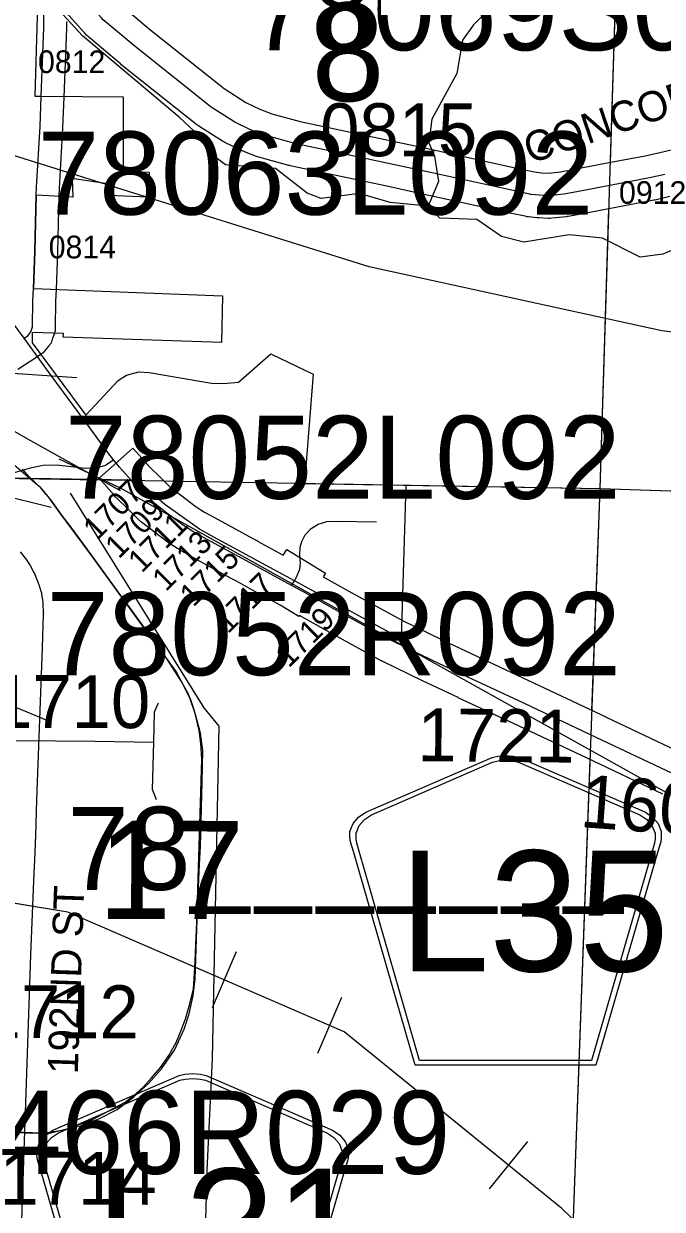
# Model space of a CAD drawing. Extents: x -132.8 to -73.3, y -60 to -26.
# Drawn here: x -120.744 to -119.898, y -53.272 to -51.702 of the extents above; entities that cross this region are included whole.
import ezdxf

# ---------------------------------------------------------------- set-up
doc = ezdxf.new("R2010")
doc.units = 0
for name, color, linetype in [('tdCoCityStreetMajor', 7, 'Continuous'), ('tdCoCityStreetMinor', 7, 'Continuous'), ('tdCoCorpBndry', 7, 'Continuous'), ('tdCoHydroRiver', 7, 'Continuous'), ('tdCoInstTxt', 7, 'Continuous'), ('tdCoPipe', 7, 'Continuous'), ('tdCoRRCL', 7, 'Continuous'), ('tdCoSecRdNmbr', 7, 'Continuous'), ('tdCoSecRdTxt', 7, 'Continuous'), ('tdCoSecRteBand', 7, 'Continuous'), ('tdCoSecRteCL', 7, 'Continuous'), ('tdCoSectLine', 7, 'Continuous'), ('tdCoSectLinePart', 7, 'Continuous'), ('tdCoSectNmbr', 7, 'Continuous'), ('tdCoShieldCoRte', 7, 'Continuous'), ('tdCoShieldCoRteHrd', 7, 'Continuous'), ('tdCoStrucPriMaintName', 7, 'Continuous'), ('tdCoSurfAsphalt', 7, 'Continuous'), ('tdCoSurfBitum', 7, 'Continuous'), ('tdCoSurfConc', 7, 'Continuous'), ('tdCoSurfConcUnbanded', 7, 'Continuous'), ('tdCoSurfGravel', 7, 'Continuous')]:
    doc.layers.add(name, color=color, linetype=linetype)

msp = doc.modelspace()

# ---------------------------------------------------------------- linework, layer by layer
at = {"layer": 'tdCoCityStreetMajor'}
msp.add_lwpolyline([(-120.6017, -52.3067), (-120.617, -52.2894), (-120.6248, -52.2797), (-120.6325, -52.2701), (-120.6564, -52.2371), (-120.6786, -52.2067), (-120.7077, -52.1678), (-120.7433, -52.1186), (-120.7581, -52.0982), (-120.8243, -52.009), (-120.927, -51.8699), (-120.9535, -51.834), (-120.9769, -51.8032)], dxfattribs=at)
at = {"layer": 'tdCoCityStreetMinor'}
for points in [[(-120.7873, -52.3034), (-120.7673, -52.2994), (-120.7333, -52.2898), (-120.718, -52.2866), (-120.7, -52.2863), (-120.6812, -52.2883), (-120.6623, -52.2905), (-120.648, -52.2903), (-120.6364, -52.2871), (-120.6248, -52.2797)], [(-120.3853, -52.4396), (-120.3829, -52.4356), (-120.3782, -52.4245), (-120.377, -52.4161), (-120.3779, -52.4058), (-120.3775, -52.3954), (-120.3755, -52.3878), (-120.3708, -52.3789), (-120.3631, -52.3703), (-120.3538, -52.3646), (-120.3422, -52.3611), (-120.3289, -52.3606), (-120.2766, -52.3616)]]:
    msp.add_lwpolyline(points, dxfattribs=at)
at = {"layer": 'tdCoCorpBndry'}
msp.add_lwpolyline([(-120.7232, -51.5858), (-120.7293, -51.7981), (-120.7208, -51.7982), (-120.6119, -51.7988), (-120.6119, -51.8983), (-120.5776, -51.8989), (-120.5788, -51.932), (-120.6317, -51.9297), (-120.6327, -51.9142), (-120.6795, -51.9071), (-120.6789, -51.9317), (-120.7273, -51.9293), (-120.7292, -52.0033), (-120.7311, -52.0527), (-120.4803, -52.0623), (-120.4818, -52.1241), (-120.6914, -52.1171), (-120.6913, -52.1124), (-120.7326, -52.111), (-120.7329, -52.1245), (-120.6618, -52.2205), (-120.6188, -52.1747), (-120.6077, -52.1673), (-120.5913, -52.1632), (-120.5777, -52.1641), (-120.4949, -52.1781), (-120.4791, -52.1787), (-120.4595, -52.1768), (-120.4164, -52.1394), (-120.3605, -52.1662), (-120.3717, -52.3108), (-120.2377, -52.3132), (-120.2436, -52.5164), (-120.3853, -52.4396), (-120.4921, -52.3818), (-120.511, -52.3713), (-120.5569, -52.3389), (-120.5929, -52.3068), (-120.6017, -52.3067), (-120.7874, -52.3034)], dxfattribs=at)
at = {"layer": 'tdCoHydroRiver'}
for points in [[(-119.8566, -51.3835), (-119.9158, -51.4151), (-119.9272, -51.4274), (-119.9372, -51.4461), (-119.9593, -51.5038), (-119.9777, -51.5444), (-120.0187, -51.6032), (-120.0457, -51.6072), (-120.0581, -51.599), (-120.0835, -51.6031), (-120.0964, -51.6153), (-120.1081, -51.6387), (-120.112, -51.667), (-120.1477, -51.7039), (-120.1625, -51.724), (-120.17, -51.768), (-120.2031, -51.8286), (-120.2071, -51.8601), (-120.1997, -51.8776), (-120.1943, -51.9109), (-120.2078, -51.9437)], [(-120.2078, -51.9437), (-120.2582, -51.9391), (-120.2989, -51.927), (-120.3496, -51.9335), (-120.3684, -51.9267), (-120.4101, -51.894), (-120.4763, -51.8891), (-120.4871, -51.8809), (-120.4977, -51.8633), (-120.5377, -51.8259), (-120.6658, -51.7183), (-120.7578, -51.618), (-120.7684, -51.6004), (-120.7694, -51.5798), (-120.7846, -51.5557), (-120.8, -51.5411), (-121.0683, -51.5418), (-121.1168, -51.5263), (-121.1402, -51.5146)], [(-119.7523, -51.9086), (-119.77, -51.9223), (-119.8164, -51.9447), (-119.8358, -51.9632), (-119.8507, -51.988), (-119.897, -52.0073), (-119.9271, -52.0112), (-119.9769, -51.9862), (-120.021, -51.9818), (-120.0812, -51.9912), (-120.111, -51.9841), (-120.1436, -51.9612), (-120.1925, -51.9598), (-120.2078, -51.9437)], [(-120.5124, -53.6489), (-120.5009, -53.2201), (-120.4938, -53.072), (-120.4851, -52.632), (-120.505, -52.6078), (-120.6821, -52.3237)]]:
    msp.add_lwpolyline(points, dxfattribs=at)
at = {"layer": 'tdCoInstTxt'}
msp.add_lwpolyline([(-119.6004, -52.1468), (-119.8985, -52.1087), (-120.2863, -52.0241), (-120.7731, -51.872), (-120.8087, -51.8239)], dxfattribs=at)
msp.add_lwpolyline([(-119.6004, -52.1468), (-119.8985, -52.1087), (-120.2863, -52.0241), (-120.7731, -51.872), (-120.8087, -51.8239)], dxfattribs=at)
at = {"layer": 'tdCoPipe'}
for p, q in [((-120.4624, -52.9309), (-120.4943, -53.0049)), ((-120.3227, -52.9913), (-120.3547, -53.0654)), ((-120.0763, -53.1821), (-120.1271, -53.2446))]:
    msp.add_line(p, q, dxfattribs=at)
for points in [[(-119.7966, -53.496), (-120.031, -53.2709), (-120.3193, -53.0367), (-120.6853, -52.8785), (-121.0012, -52.8266), (-121.4905, -52.4057), (-121.3998, -51.5572), (-121.2369, -50.9128), (-120.9144, -50.4185), (-120.4009, -49.5883), (-120.2556, -49.2317), (-120.1948, -48.5733), (-120.2234, -47.9788), (-119.9584, -47.7616), (-119.9471, -47.3844)], [(-120.4784, -52.968), (-120.6853, -52.8785), (-120.7602, -52.8662)], [(-120.1017, -53.2134), (-120.3193, -53.0367), (-120.3387, -53.0283)]]:
    msp.add_lwpolyline(points, dxfattribs=at)
at = {"layer": 'tdCoRRCL'}
msp.add_line((-120.7391, -52.2518), (-120.616, -52.32), dxfattribs=at)
for points in [[(-121.1776, -51.8759), (-120.848, -52.189), (-120.7391, -52.2518)], [(-120.6972, -52.2782), (-120.6161, -52.3166), (-119.5675, -52.901), (-119.4875, -52.922), (-119.4101, -52.9193), (-119.3464, -52.8957), (-119.2742, -52.8534), (-118.8703, -52.5563), (-118.7896, -52.5458), (-118.7219, -52.5523), (-118.6702, -52.5695), (-118.4084, -52.6978), (-118.1016, -52.8573), (-117.8806, -52.9782), (-117.8049, -53.0417), (-117.7743, -53.0804), (-117.6699, -53.3151)], [(-120.8232, -53.1664), (-120.7098, -53.1712), (-120.6833, -53.1642), (-120.6526, -53.1529), (-120.6094, -53.1299), (-120.5951, -53.1183), (-120.5848, -53.1091), (-120.5744, -53.0976), (-120.5628, -53.0842), (-120.5516, -53.0684), (-120.5417, -53.0511), (-120.5356, -53.036), (-120.5296, -53.0198), (-120.5236, -52.9996), (-120.5189, -52.98), (-120.5172, -52.9521), (-120.5147, -52.8917), (-120.5079, -52.6759), (-120.5092, -52.6552), (-120.5115, -52.6381), (-120.5168, -52.6155), (-120.5187, -52.6081), (-120.522, -52.5985), (-120.526, -52.5889), (-120.5338, -52.575), (-120.542, -52.5597), (-120.6036, -52.4748), (-120.6201, -52.4526), (-120.6545, -52.4049), (-120.6803, -52.3702), (-120.6934, -52.3528), (-120.7075, -52.333), (-120.714, -52.3253), (-120.7214, -52.3166), (-120.7287, -52.3103), (-120.7566, -52.2868)], [(-120.7727, -53.169), (-120.7334, -53.171), (-120.7124, -53.17), (-120.6909, -53.1666), (-120.6687, -53.1613), (-120.6445, -53.1519), (-120.6202, -53.1396), (-120.5979, -53.1228), (-120.5787, -53.1052), (-120.5612, -53.0858), (-120.5441, -53.0612), (-120.5313, -53.0334), (-120.5245, -53.013), (-120.5192, -52.9889), (-120.5169, -52.9666), (-120.5135, -52.8751), (-120.5108, -52.8155), (-120.5098, -52.7917), (-120.5074, -52.7063), (-120.5067, -52.6643), (-120.5098, -52.6413), (-120.5161, -52.6169), (-120.5237, -52.5946), (-120.535, -52.5731), (-120.5588, -52.5361), (-120.5782, -52.5107), (-120.655, -52.4048), (-120.6967, -52.3484), (-120.7114, -52.328), (-120.7198, -52.3178), (-120.7362, -52.3027), (-120.7455, -52.292)]]:
    msp.add_lwpolyline(points, dxfattribs=at)
at = {"layer": 'tdCoSecRteBand'}
for points in [[(-120.6179, -51.6751), (-120.5774, -51.7093), (-120.4783, -51.7881), (-120.4496, -51.8063), (-120.4312, -51.8152), (-120.4252, -51.8175), (-120.4153, -51.8214), (-120.3775, -51.8316), (-120.2504, -51.8587), (-120.2148, -51.8663), (-120.2147, -51.8663), (-120.2146, -51.8663), (-120.0849, -51.8946), (-120.0671, -51.8984), (-120.0579, -51.8995), (-120.0483, -51.8999), (-120.0324, -51.8982), (-120.0166, -51.8952), (-119.9707, -51.8865), (-119.9206, -51.877), (-119.901, -51.8725), (-119.8628, -51.8638)], [(-120.6872, -51.6994), (-120.6874, -51.7083), (-120.6874, -51.7085), (-120.6874, -51.7087), (-120.6908, -51.7993), (-120.6924, -51.8397), (-120.6924, -51.84), (-120.6924, -51.8403), (-120.697, -51.92), (-120.6973, -51.9301), (-120.6992, -52.0041), (-120.6992, -52.0042), (-120.6993, -52.0044), (-120.7011, -52.0539), (-120.7017, -52.0697), (-120.7022, -52.1041), (-120.7023, -52.1087), (-120.7037, -52.1131), (-120.706, -52.1198), (-120.7077, -52.125), (-120.7111, -52.1292), (-120.7153, -52.1344), (-120.7182, -52.1379), (-120.722, -52.1404), (-120.7267, -52.1436), (-120.7517, -52.1602)], [(-119.8876, -51.931), (-119.9078, -51.9356), (-119.9084, -51.9357), (-119.9089, -51.9358), (-119.9595, -51.9455), (-120.0054, -51.9542), (-120.0224, -51.9574), (-120.0236, -51.9576), (-120.0248, -51.9578), (-120.0443, -51.9598), (-120.0466, -51.9601), (-120.049, -51.96), (-120.0617, -51.9593), (-120.0626, -51.9593), (-120.0635, -51.9592), (-120.0752, -51.9579), (-120.0767, -51.9578), (-120.0782, -51.9574), (-120.0796, -51.9571), (-120.0976, -51.9533), (-120.0976, -51.9533), (-120.0976, -51.9533), (-120.2273, -51.925), (-120.2629, -51.9174), (-120.3908, -51.8902), (-120.3916, -51.89), (-120.3924, -51.8898), (-120.4325, -51.8789), (-120.434, -51.8785), (-120.4355, -51.8779), (-120.4469, -51.8735), (-120.454, -51.8707), (-120.4552, -51.8703), (-120.4563, -51.8698), (-120.4774, -51.8595), (-120.4789, -51.8588), (-120.4803, -51.8579), (-120.5118, -51.8379), (-120.5132, -51.837), (-120.5144, -51.836), (-120.6151, -51.756), (-120.6154, -51.7557), (-120.6158, -51.7554), (-120.6578, -51.7199), (-120.6591, -51.7189), (-120.6602, -51.7177), (-120.6631, -51.7147), (-120.6634, -51.7143), (-120.6638, -51.7139), (-120.687, -51.6877)], [(-119.8969, -52.7221), (-119.998, -52.6743), (-120.1015, -52.6255), (-120.1682, -52.5945), (-120.1683, -52.5944), (-120.1684, -52.5944), (-120.2153, -52.5722), (-120.2154, -52.5721), (-120.2156, -52.5721), (-120.2688, -52.5462), (-120.2695, -52.5459), (-120.2701, -52.5455), (-120.3382, -52.5083), (-120.3383, -52.5082), (-120.3384, -52.5081), (-120.3785, -52.4857), (-120.3794, -52.4872), (-120.4041, -52.472), (-120.412, -52.4678), (-120.4122, -52.4677), (-120.4297, -52.4585), (-120.4295, -52.4581), (-120.4629, -52.4397), (-120.469, -52.4365), (-120.5151, -52.4114), (-120.5154, -52.4113), (-120.5156, -52.4112), (-120.5343, -52.4005), (-120.5349, -52.4002), (-120.5355, -52.3998), (-120.5481, -52.392), (-120.5491, -52.3913), (-120.5501, -52.3906), (-120.5723, -52.3741), (-120.5725, -52.3739), (-120.5727, -52.3738), (-120.5877, -52.3622), (-120.5891, -52.3611), (-120.5904, -52.3598), (-120.6037, -52.3468), (-120.6214, -52.3296), (-120.6222, -52.3288), (-120.623, -52.3279), (-120.6242, -52.3265), (-120.6242, -52.3265), (-120.6441, -52.304), (-120.5991, -52.2643), (-120.5792, -52.2868), (-120.5792, -52.2868), (-120.5792, -52.2868), (-120.5792, -52.2869), (-120.5787, -52.2874), (-120.5618, -52.3039), (-120.5617, -52.3039), (-120.5617, -52.304), (-120.5497, -52.3158), (-120.5362, -52.3261), (-120.5152, -52.3418), (-120.5042, -52.3487), (-120.4863, -52.3588), (-120.4403, -52.3837), (-120.4342, -52.387), (-120.4342, -52.3871), (-120.4341, -52.3871), (-120.3999, -52.406), (-120.3952, -52.3983), (-120.3441, -52.4298), (-120.347, -52.4346), (-120.3093, -52.4557), (-120.2419, -52.4925), (-120.1895, -52.518), (-120.1428, -52.5401), (-120.0761, -52.5712), (-120.076, -52.5712), (-120.076, -52.5712), (-119.9724, -52.62), (-119.9724, -52.6201), (-119.9723, -52.6201), (-119.8713, -52.6679)], [(-120.7484, -52.4012), (-120.742, -52.4098), (-120.7417, -52.4103), (-120.7413, -52.4108), (-120.7371, -52.417), (-120.7363, -52.4182), (-120.7355, -52.4196), (-120.7306, -52.4287), (-120.7298, -52.4301), (-120.7292, -52.4316), (-120.7248, -52.4425), (-120.7243, -52.4436), (-120.7239, -52.4448), (-120.7212, -52.4535), (-120.7205, -52.4556), (-120.7202, -52.4579), (-120.7187, -52.4675), (-120.7185, -52.4691), (-120.7184, -52.4707), (-120.7179, -52.4813), (-120.7178, -52.4825), (-120.7179, -52.4838), (-120.7196, -52.5287), (-120.727, -52.7298), (-120.7285, -52.7763), (-120.7285, -52.7765), (-120.7285, -52.7766), (-120.7298, -52.8094), (-120.7305, -52.8263), (-120.7349, -52.9348), (-120.7418, -53.1436), (-120.7418, -53.1436), (-120.7418, -53.1436), (-120.7431, -53.1809), (-120.7431, -53.181), (-120.7431, -53.181), (-120.7431, -53.181), (-120.748, -53.3258)]]:
    msp.add_lwpolyline(points, dxfattribs=at)
at = {"layer": 'tdCoSecRteCL'}
msp.add_line((-120.3892, -52.4459), (-120.3853, -52.4396), dxfattribs=at)
for points in [[(-119.8943, -51.9017), (-119.9145, -51.9064), (-119.9651, -51.916), (-120.011, -51.9247), (-120.028, -51.9279), (-120.0475, -51.93), (-120.0603, -51.9294), (-120.0719, -51.9281), (-120.0733, -51.9278), (-120.0913, -51.9239), (-120.221, -51.8957), (-120.2567, -51.8881), (-120.3845, -51.8608), (-120.4246, -51.8499), (-120.4361, -51.8455), (-120.4432, -51.8428), (-120.4643, -51.8325), (-120.4957, -51.8126), (-120.5964, -51.7325), (-120.6385, -51.697), (-120.6413, -51.694), (-120.7123, -51.6137), (-120.716, -51.5974), (-120.7161, -51.5863)], [(-120.7433, -52.1186), (-120.7386, -52.1155), (-120.7344, -52.1103), (-120.7322, -52.1036), (-120.7317, -52.0689), (-120.7311, -52.0527), (-120.7292, -52.0033), (-120.7273, -51.9293), (-120.727, -51.9187), (-120.7223, -51.8385), (-120.7208, -51.7982), (-120.7174, -51.7076), (-120.7172, -51.6987), (-120.7168, -51.6778)], [(-120.3892, -52.4459), (-120.398, -52.4413), (-120.4486, -52.4134), (-120.4546, -52.4101), (-120.5008, -52.385), (-120.5196, -52.3744), (-120.5322, -52.3665), (-120.5543, -52.35), (-120.5694, -52.3384), (-120.5827, -52.3254), (-120.6005, -52.3081), (-120.6017, -52.3067), (-120.6017, -52.3067)], [(-119.7505, -52.7553), (-119.764, -52.75), (-119.7788, -52.7434), (-119.8212, -52.7244), (-119.8841, -52.695), (-119.9852, -52.6472), (-120.0888, -52.5984), (-120.1556, -52.5673), (-120.2024, -52.5451), (-120.2557, -52.5192), (-120.3238, -52.482), (-120.3741, -52.4538), (-120.3892, -52.4459)], [(-120.5715, -52.6535), (-120.5704, -52.6132), (-120.5655, -52.6013)], [(-120.7541, -52.6512), (-120.6495, -52.652), (-120.5715, -52.6535)], [(-120.5678, -52.7299), (-120.5733, -52.7159), (-120.5715, -52.6535)]]:
    msp.add_lwpolyline(points, dxfattribs=at)
at = {"layer": 'tdCoSectLine'}
for points in [[(-119.9802, -52.3177), (-119.9485, -51.3215)], [(-120.9864, -52.2999), (-119.9802, -52.3177)], [(-120.0166, -53.3198), (-119.9802, -52.3177)], [(-119.9802, -52.3177), (-118.9893, -52.35)]]:
    msp.add_lwpolyline(points, dxfattribs=at)
at = {"layer": 'tdCoSectLinePart'}
for points in [[(-119.9665, -51.8857), (-119.9499, -51.3639)], [(-119.9802, -52.3177), (-119.9684, -51.9471)], [(-120.75, -52.3041), (-120.6427, -52.306)], [(-120.372, -52.3108), (-119.9802, -52.3177)], [(-119.9909, -52.6114), (-119.9802, -52.3177)], [(-119.9802, -52.3177), (-119.7684, -52.3246)], [(-120.0166, -53.3198), (-119.9933, -52.6769)]]:
    msp.add_lwpolyline(points, dxfattribs=at)
at = {"layer": 'tdCoShieldCoRte'}
for points in [[(-120.6398, -53.5022), (-120.7217, -53.2193), (-120.7256, -53.2062), (-120.7263, -53.2003), (-120.7263, -53.1925), (-120.7221, -53.1822), (-120.7148, -53.1737), (-120.7052, -53.167), (-120.538, -53.0946), (-120.5304, -53.093), (-120.52, -53.0921), (-120.5096, -53.093), (-120.5021, -53.0946), (-120.3348, -53.167), (-120.3252, -53.1737), (-120.318, -53.1822), (-120.3137, -53.1925), (-120.3137, -53.2003), (-120.3144, -53.2062), (-120.3183, -53.2193), (-120.4003, -53.5022)], [(-120.6339, -53.4959), (-120.7137, -53.2206), (-120.7174, -53.208), (-120.7181, -53.2023), (-120.7181, -53.1948), (-120.714, -53.1849), (-120.707, -53.1768), (-120.6978, -53.1704), (-120.5372, -53.1009), (-120.53, -53.0994), (-120.52, -53.0985), (-120.51, -53.0994), (-120.5028, -53.1009), (-120.3422, -53.1704), (-120.333, -53.1768), (-120.326, -53.1849), (-120.322, -53.1948), (-120.322, -53.2023), (-120.3227, -53.208), (-120.3264, -53.2206), (-120.4061, -53.4959)]]:
    msp.add_lwpolyline(points, close=True, dxfattribs=at)
at = {"layer": 'tdCoShieldCoRteHrd'}
for points in [[(-120.2251, -53.0812), (-120.3071, -52.7983), (-120.3109, -52.7852), (-120.3117, -52.7793), (-120.3117, -52.7715), (-120.3074, -52.7611), (-120.3001, -52.7527), (-120.2906, -52.746), (-120.1233, -52.6736), (-120.1158, -52.672), (-120.1054, -52.6711), (-120.0949, -52.672), (-120.0874, -52.6736), (-119.9201, -52.746), (-119.9106, -52.7527), (-119.9033, -52.7611), (-119.899, -52.7715), (-119.899, -52.7793), (-119.8998, -52.7852), (-119.9037, -52.7983), (-119.9856, -53.0812)], [(-120.2193, -53.0749), (-120.299, -52.7996), (-120.3027, -52.787), (-120.3034, -52.7813), (-120.3034, -52.7738), (-120.2993, -52.7639), (-120.2924, -52.7558), (-120.2832, -52.7494), (-120.1226, -52.6799), (-120.1154, -52.6783), (-120.1054, -52.6775), (-120.0953, -52.6783), (-120.0881, -52.6799), (-119.9275, -52.7494), (-119.9184, -52.7558), (-119.9114, -52.7639), (-119.9073, -52.7738), (-119.9073, -52.7813), (-119.908, -52.787), (-119.9117, -52.7996), (-119.9915, -53.0749)]]:
    msp.add_lwpolyline(points, close=True, dxfattribs=at)
at = {"layer": 'tdCoStrucPriMaintName'}
for p, q in [((-120.6737, -52.1711), (-121.5022, -52.1143)), ((-120.6737, -52.1711), (-121.5022, -52.1143)), ((-120.6737, -52.1711), (-121.5022, -52.1143)), ((-120.7077, -52.3428), (-121.4594, -52.1563)), ((-120.7077, -52.3428), (-121.4594, -52.1563)), ((-120.7077, -52.3428), (-121.4594, -52.1563)), ((-120.7077, -52.627), (-121.4353, -52.3257)), ((-120.7077, -52.627), (-121.4353, -52.3257)), ((-120.7077, -52.627), (-121.4353, -52.3257))]:
    msp.add_line(p, q, dxfattribs=at)
at = {"layer": 'tdCoSurfAsphalt'}
msp.add_lwpolyline([(-119.8841, -52.695), (-119.9852, -52.6472), (-120.0888, -52.5984), (-120.1556, -52.5673), (-120.2024, -52.5451), (-120.2557, -52.5192), (-120.3238, -52.482), (-120.3741, -52.4538), (-120.3892, -52.4459), (-120.398, -52.4413), (-120.4486, -52.4134), (-120.4546, -52.4101), (-120.5008, -52.385), (-120.5196, -52.3744)], dxfattribs=at)
at = {"layer": 'tdCoSurfBitum'}
for points in [[(-120.7433, -52.1186), (-120.7386, -52.1155), (-120.7344, -52.1103), (-120.7322, -52.1036), (-120.7317, -52.0689), (-120.7311, -52.0527), (-120.7292, -52.0033), (-120.7273, -51.9293), (-120.727, -51.9187), (-120.7223, -51.8385), (-120.7208, -51.7982), (-120.7174, -51.7076), (-120.7172, -51.6987), (-120.7168, -51.6778)], [(-119.8943, -51.9017), (-119.9145, -51.9064), (-119.9651, -51.916), (-120.011, -51.9247), (-120.028, -51.9279), (-120.0475, -51.93), (-120.0603, -51.9294), (-120.0719, -51.9281), (-120.0733, -51.9278), (-120.0913, -51.9239), (-120.221, -51.8957), (-120.2567, -51.8881), (-120.3845, -51.8608), (-120.4246, -51.8499), (-120.4361, -51.8455), (-120.4432, -51.8428), (-120.4643, -51.8325), (-120.4957, -51.8126), (-120.5964, -51.7325), (-120.6385, -51.697)]]:
    msp.add_lwpolyline(points, dxfattribs=at)
at = {"layer": 'tdCoSurfConc'}
msp.add_lwpolyline([(-120.5196, -52.3744), (-120.5322, -52.3665), (-120.5543, -52.35), (-120.5694, -52.3384), (-120.5827, -52.3254), (-120.6005, -52.3081), (-120.6017, -52.3067), (-120.6017, -52.3067)], dxfattribs=at)
at = {"layer": 'tdCoSurfConcUnbanded'}
for points in [[(-120.5715, -52.6535), (-120.5704, -52.6132), (-120.5655, -52.6013)], [(-120.7541, -52.6512), (-120.6495, -52.652), (-120.5715, -52.6535)], [(-120.5678, -52.7299), (-120.5733, -52.7159), (-120.5715, -52.6535)]]:
    msp.add_lwpolyline(points, dxfattribs=at)
at = {"layer": 'tdCoSurfGravel'}
msp.add_line((-120.3892, -52.4459), (-120.3853, -52.4396), dxfattribs=at)

# ---------------------------------------------------------------- texts
at = {"layer": 'tdCoSecRdNmbr'}
for s, height, rotation, p in [('0812', 0.03, 359.91, (-120.725, -51.7675)), ('0815', 0.07, 359.9104, (-120.3512, -51.8775)), ('0912', 0.03, 359.9105, (-119.9551, -51.9406)), ('0814', 0.03, 359.91, (-120.7108, -52.0128)), ('1707', 0.03, 44.9112, (-120.647, -52.3875)), ('1709', 0.03, 44.9112, (-120.6179, -52.4117)), ('1711', 0.03, 44.9112, (-120.5875, -52.4306)), ('1713', 0.03, 44.9112, (-120.5554, -52.4549)), ('1715', 0.03, 44.9112, (-120.5191, -52.4755)), ('1717', 0.03, 44.9112, (-120.4731, -52.5107)), ('1719', 0.03, 44.9112, (-120.3926, -52.556)), ('1710', 0.07, 359.91, (-120.7845, -52.6345)), ('1721', 0.07, 359.4532, (-120.2224, -52.6785)), ('1607', 0.07, 355.8137, (-120.0079, -52.7657)), ('1712', 0.07, 359.91, (-120.7997, -53.0451)), ('1714', 0.07, 359.91, (-120.776, -53.2656))]:
    msp.add_text(s, height=height, rotation=rotation, dxfattribs=at).set_placement(p)
at = {"layer": 'tdCoSecRdTxt'}
for s, rotation, p in [('CONCORD', 18.8743, (-120.0728, -51.888)), ('192ND ST', 88.0267, (-120.6723, -53.0934))]:
    msp.add_text(s, height=0.04, rotation=rotation, dxfattribs=at).set_placement(p)
at = {"layer": 'tdCoSectNmbr'}
for s, rotation, p in [('8', 359.9102, (-120.3625, -51.8045)), ('17', 359.9101, (-120.6453, -52.8873))]:
    msp.add_text(s, height=0.13, rotation=rotation, dxfattribs=at).set_placement(p)
at = {"layer": 'tdCoShieldCoRte'}
msp.add_text('L31', height=0.16, dxfattribs=at).set_placement((-120.6487, -53.378))
at = {"layer": 'tdCoShieldCoRteHrd'}
msp.add_text('L35', height=0.16, dxfattribs=at).set_placement((-120.246, -52.9569))
at = {"layer": 'tdCoStrucPriMaintName'}
for s, p in [('78069S092', (-120.4445, -51.7374)), ('78069S092', (-120.4445, -51.7374)), ('78069S092', (-120.4445, -51.7374)), ('78063L092', (-120.7256, -51.955)), ('78063L092', (-120.7256, -51.955)), ('78063L092', (-120.7256, -51.955)), ('78052L092', (-120.6892, -52.3312)), ('78052L092', (-120.6892, -52.3312)), ('78052L092', (-120.6892, -52.3312)), ('78052R092', (-120.7134, -52.5647)), ('78052R092', (-120.7134, -52.5647)), ('78052R092', (-120.7134, -52.5647)), ('78_______', (-120.6863, -52.849)), ('78_______', (-120.6863, -52.849)), ('78_______', (-120.6863, -52.849)), ('78466R029', (-120.9393, -53.2249)), ('78466R029', (-120.9393, -53.2249)), ('78466R029', (-120.9393, -53.2249))]:
    msp.add_text(s, height=0.11, dxfattribs=at).set_placement(p)

doc.saveas('drawing.dxf')
